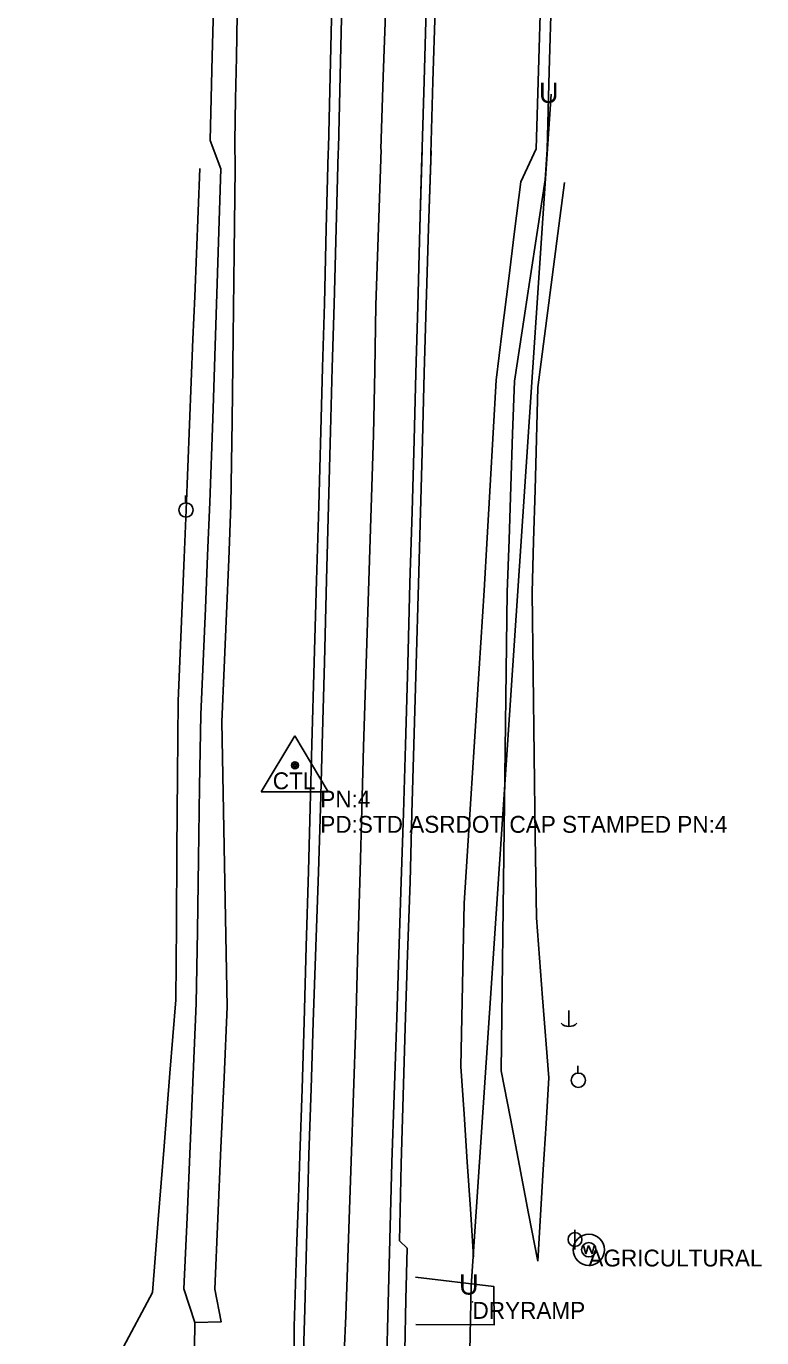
# Model space of a CAD drawing. Extents: x 1445297 to 1476720, y 2042269 to 2057889.
# Drawn here: x 1446022.3 to 1446240.4, y 2044766.6 to 2045155.5 of the extents above; entities that cross this region are included whole.
import ezdxf

# ---------------------------------------------------------------- set-up
doc = ezdxf.new("R2010")
doc.units = 0
for name, color, linetype in [('S_DITCHLINE', 7, 'Continuous'), ('S_DRIVEWAY', 7, 'Continuous'), ('S_EDGE_PAVEMENT', 7, 'Continuous'), ('S_MSC_PT_SYM', 7, 'Continuous'), ('S_PAVEMENT_CROWN', 7, 'Continuous'), ('S_PRIMARY_CTL', 7, 'Continuous'), ('S_PRIMARY_CTL_ANNOT', 7, 'Continuous'), ('S_SHOULDER', 7, 'Continuous'), ('S_SURVEY_TEXT_ANNOT', 7, 'Continuous'), ('S_UNDERGROUND_CABLE', 7, 'Continuous'), ('S_UTILITY_POLE', 7, 'Continuous'), ('S_UTL_PT_SYM', 7, 'Continuous'), ('S_WATER_WELL', 7, 'Continuous'), ('S_WATER_WELL_ANNOT', 7, 'Continuous')]:
    doc.layers.add(name, color=color, linetype=linetype)

msp = doc.modelspace()

# ---------------------------------------------------------------- linework, layer by layer
at = {"layer": 'S_DITCHLINE'}
for points in [[(1446072.33, 2044771.09), (1446069.05, 2044781.13), (1446069.97, 2044802.28), (1446070.88, 2044823.43), (1446071.79, 2044844.59), (1446072.7, 2044865.74), (1446073.04, 2044887.14), (1446073.37, 2044908.54), (1446073.71, 2044929.94), (1446074.04, 2044951.34), (1446074.72, 2044967.08), (1446075.4, 2044982.82), (1446076.08, 2044998.56), (1446076.76, 2045014.3), (1446077.58, 2045039.02), (1446078.4, 2045063.73), (1446079.21, 2045088.45), (1446080.03, 2045113.16), (1446076.86, 2045121.6), (1446077.47, 2045146.56), (1446078.08, 2045171.52)], [(1446154.93, 2044790.57), (1446154, 2044804.68), (1446153.07, 2044818.79), (1446152.13, 2044832.9), (1446151.2, 2044847.01), (1446151.69, 2044871.22), (1446152.19, 2044895.44), (1446153.66, 2044918.62), (1446155.14, 2044941.81), (1446156.61, 2044964.99), (1446158.09, 2044988.17), (1446158.97, 2045003.75), (1446159.84, 2045019.32), (1446160.72, 2045034.9), (1446161.6, 2045050.48), (1446163.43, 2045065.18), (1446165.26, 2045079.89), (1446167.09, 2045094.59), (1446168.92, 2045109.3), (1446173.55, 2045119.16), (1446174.22, 2045142.36), (1446174.88, 2045165.56)], [(1446163.17, 2044845.71), (1446163.43, 2044869.9), (1446163.68, 2044894.09), (1446164, 2044917.47), (1446164.31, 2044940.86), (1446164.62, 2044964.24), (1446164.93, 2044987.63), (1446165.47, 2045003.29), (1446166, 2045018.95), (1446166.54, 2045034.61), (1446167.08, 2045050.27), (1446169.35, 2045065.19), (1446171.62, 2045080.12), (1446173.88, 2045095.04), (1446176.15, 2045109.96), (1446176.78, 2045118.94), (1446177.41, 2045142.16), (1446178.04, 2045165.38)], [(1446072.06, 2044755.83), (1446072.33, 2044771.09), (1446080.14, 2044771.35), (1446078.2, 2044781), (1446079.12, 2044801.93), (1446080.03, 2044822.86), (1446080.94, 2044843.78), (1446081.86, 2044864.71), (1446081.47, 2044885.83), (1446081.09, 2044906.95), (1446080.7, 2044928.07), (1446080.32, 2044949.19), (1446080.99, 2044965.26), (1446081.65, 2044981.32), (1446082.32, 2044997.38), (1446082.99, 2045013.45), (1446083.31, 2045038.44), (1446083.64, 2045063.43), (1446083.96, 2045088.42), (1446084.29, 2045113.41), (1446084.18, 2045121.29), (1446084.39, 2045133.79), (1446084.6, 2045146.3), (1446084.8, 2045158.81)], [(1446059.69, 2044779.98), (1446061.43, 2044801.68), (1446063.17, 2044823.37), (1446064.91, 2044845.07), (1446066.65, 2044866.76), (1446066.82, 2044888.93), (1446066.99, 2044911.1), (1446067.16, 2044933.26), (1446067.33, 2044955.43), (1446067.91, 2044969.58), (1446068.5, 2044983.73), (1446069.08, 2044997.88), (1446069.67, 2045012.03), (1446070.19, 2045024.68), (1446070.7, 2045037.34), (1446071.22, 2045049.99), (1446071.73, 2045062.64), (1446072.25, 2045075.3), (1446072.76, 2045087.95), (1446073.28, 2045100.6), (1446073.79, 2045113.25)], [(1446059.69, 2044779.98), (1446061.43, 2044801.68), (1446063.17, 2044823.37), (1446064.91, 2044845.07), (1446066.65, 2044866.76), (1446066.82, 2044888.93), (1446066.99, 2044911.1), (1446067.16, 2044933.26), (1446067.33, 2044955.43), (1446067.91, 2044969.58), (1446068.5, 2044983.73), (1446069.08, 2044997.88), (1446069.67, 2045012.03), (1446070.19, 2045024.68), (1446070.7, 2045037.34), (1446071.22, 2045049.99), (1446071.73, 2045062.64), (1446072.25, 2045075.3), (1446072.76, 2045087.95), (1446073.28, 2045100.6), (1446073.79, 2045113.25)], [(1446072.33, 2044771.09), (1446069.05, 2044781.13), (1446069.97, 2044802.28), (1446070.88, 2044823.43), (1446071.79, 2044844.59), (1446072.7, 2044865.74), (1446073.04, 2044887.14), (1446073.37, 2044908.54), (1446073.71, 2044929.94), (1446074.04, 2044951.34), (1446074.72, 2044967.08), (1446075.4, 2044982.82), (1446076.08, 2044998.56), (1446076.76, 2045014.3), (1446077.58, 2045039.02), (1446078.4, 2045063.73), (1446079.21, 2045088.45), (1446080.03, 2045113.16)], [(1446071.26, 2044710.05), (1446071.53, 2044725.31), (1446071.79, 2044740.57), (1446072.06, 2044755.83), (1446072.33, 2044771.09), (1446080.14, 2044771.35), (1446078.2, 2044781), (1446079.12, 2044801.93), (1446080.03, 2044822.86), (1446080.94, 2044843.78), (1446081.86, 2044864.71), (1446081.47, 2044885.83), (1446081.09, 2044906.95), (1446080.7, 2044928.07), (1446080.32, 2044949.19), (1446080.99, 2044965.26), (1446081.65, 2044981.32), (1446082.32, 2044997.38), (1446082.99, 2045013.45), (1446083.31, 2045038.44), (1446083.64, 2045063.43), (1446083.96, 2045088.42), (1446084.29, 2045113.41)], [(1446168.92, 2045109.3), (1446167.09, 2045094.59), (1446165.26, 2045079.89), (1446163.43, 2045065.18), (1446161.6, 2045050.48), (1446160.72, 2045034.9), (1446159.84, 2045019.32), (1446158.97, 2045003.75), (1446158.09, 2044988.17), (1446156.61, 2044964.99), (1446155.14, 2044941.81), (1446153.66, 2044918.62), (1446152.19, 2044895.44), (1446151.69, 2044871.22), (1446151.2, 2044847.01), (1446152.13, 2044832.9), (1446153.07, 2044818.79), (1446154, 2044804.68), (1446154.93, 2044790.57)], [(1446176.15, 2045109.96), (1446173.88, 2045095.04), (1446171.62, 2045080.12), (1446169.35, 2045065.19), (1446167.08, 2045050.27), (1446166.54, 2045034.61), (1446166, 2045018.95), (1446165.47, 2045003.29), (1446164.93, 2044987.63), (1446164.62, 2044964.24), (1446164.31, 2044940.86), (1446164, 2044917.47), (1446163.68, 2044894.09), (1446163.43, 2044869.9), (1446163.17, 2044845.71)], [(1446181.94, 2045109.16), (1446179.96, 2045093.96), (1446177.99, 2045078.77), (1446176.02, 2045063.57), (1446174.04, 2045048.37), (1446173.61, 2045033.16), (1446173.18, 2045017.96), (1446172.75, 2045002.75), (1446172.32, 2044987.54), (1446172.63, 2044963.44), (1446172.94, 2044939.34), (1446173.26, 2044915.24), (1446173.57, 2044891.14), (1446175.43, 2044867.41), (1446177.28, 2044843.68), (1446176.46, 2044830.08), (1446175.63, 2044816.49), (1446174.81, 2044802.9), (1446173.98, 2044789.31)], [(1446163.17, 2044845.71), (1446165.88, 2044831.61), (1446168.58, 2044817.51), (1446171.28, 2044803.41), (1446173.98, 2044789.31)], [(1446059.69, 2044779.98), (1446050.34, 2044762.42), (1446040.99, 2044744.86), (1446031.63, 2044727.3), (1446022.28, 2044709.74)]]:
    msp.add_lwpolyline(points, dxfattribs=at)
at = {"layer": 'S_DRIVEWAY'}
msp.add_lwpolyline([(1446137.77, 2044784.59), (1446160.92, 2044781.78), (1446161.02, 2044770.41), (1446137.87, 2044770.54)], dxfattribs=at)
at = {"layer": 'S_EDGE_PAVEMENT'}
for points in [[(1446104.51, 2044762.35), (1446104.92, 2044775.04), (1446105.49, 2044797.93), (1446106.07, 2044820.82), (1446106.74, 2044840.5), (1446107.42, 2044860.18), (1446108.2, 2044882.46), (1446108.98, 2044904.73), (1446109.53, 2044923.61), (1446110.08, 2044942.48), (1446110.71, 2044966.9), (1446111.35, 2044991.32), (1446111.93, 2045013.34), (1446112.52, 2045035.37), (1446113.05, 2045054.21), (1446113.58, 2045073.05), (1446114.17, 2045095.47), (1446114.77, 2045117.9), (1446114.85, 2045119.28), (1446115.39, 2045140.74), (1446115.92, 2045162.21)], [(1446129.22, 2044761.27), (1446129.55, 2044772.98), (1446130.14, 2044795.76), (1446130.73, 2044818.54), (1446131.43, 2044838.55), (1446132.14, 2044858.56), (1446132.83, 2044880.24), (1446133.51, 2044901.91), (1446134.12, 2044922.1), (1446134.73, 2044942.3), (1446135.41, 2044966.32), (1446136.09, 2044990.33), (1446136.69, 2045011.54), (1446137.29, 2045032.75), (1446137.86, 2045052.62), (1446138.43, 2045072.5), (1446139.04, 2045095.65), (1446139.61, 2045116.7), (1446139.74, 2045119.55), (1446140.3, 2045139.21), (1446140.91, 2045160.63)], [(1446129.22, 2044761.27), (1446129.55, 2044772.98), (1446130.14, 2044795.76), (1446130.73, 2044818.54), (1446131.43, 2044838.55), (1446132.14, 2044858.56), (1446132.83, 2044880.24), (1446133.51, 2044901.91), (1446134.12, 2044922.1), (1446134.73, 2044942.3), (1446135.41, 2044966.32), (1446136.09, 2044990.33), (1446136.69, 2045011.54), (1446137.29, 2045032.75), (1446137.86, 2045052.62), (1446138.43, 2045072.5), (1446139.04, 2045095.65), (1446139.66, 2045118.81)]]:
    msp.add_lwpolyline(points, dxfattribs=at)
at = {"layer": 'S_MSC_PT_SYM'}
msp.add_lwpolyline([(1446154.63, 2044777.19), (1446154.63, 2044777.24), (1446154.63, 2044777.19), (1446154.58, 2044777.19), (1446154.63, 2044777.19), (1446154.63, 2044777.14), (1446154.63, 2044777.19), (1446154.68, 2044777.19)], dxfattribs=at)
at = {"layer": 'S_PAVEMENT_CROWN'}
msp.add_lwpolyline([(1446116.61, 2044761.99), (1446117.03, 2044773.09), (1446117.84, 2044796.01), (1446118.66, 2044818.92), (1446119.33, 2044839.1), (1446119.99, 2044859.28), (1446120.67, 2044882.09), (1446121.35, 2044904.9), (1446121.85, 2044923.35), (1446122.34, 2044941.81), (1446123.11, 2044966.43), (1446123.87, 2044991.05), (1446124.56, 2045012.67), (1446125.26, 2045034.29), (1446125.62, 2045053.51), (1446125.99, 2045072.73), (1446126.76, 2045095.83), (1446127.52, 2045118.93), (1446127.44, 2045119.04), (1446128.16, 2045140.5), (1446128.89, 2045161.96)], dxfattribs=at)
at = {"layer": 'S_PRIMARY_CTL'}
for p, q in [((1446101.98, 2044945.01), (1446091.95, 2044928.5)), ((1446101.98, 2044945.01), (1446111.81, 2044928.5)), ((1446091.95, 2044928.5), (1446111.81, 2044928.5))]:
    msp.add_line(p, q, dxfattribs=at)
for radius in [1.04, 0.609, 0.344]:
    msp.add_circle((1446101.98, 2044936.31), radius, dxfattribs=at)
at = {"layer": 'S_SHOULDER'}
for points in [[(1446101.75, 2044762.2), (1446101.73, 2044769.88), (1446102.15, 2044782.56), (1446102.57, 2044795.25), (1446102.99, 2044807.93), (1446103.41, 2044820.61), (1446104.07, 2044840.43), (1446104.72, 2044860.24), (1446105.35, 2044882.57), (1446105.99, 2044904.9), (1446106.5, 2044923.76), (1446107.02, 2044942.63), (1446107.71, 2044966.88), (1446108.4, 2044991.13), (1446109.02, 2045013.27), (1446109.64, 2045035.41), (1446110.17, 2045054.32), (1446110.7, 2045073.22), (1446111.27, 2045095.53), (1446111.85, 2045117.84), (1446111.96, 2045119.38), (1446112.44, 2045140.66), (1446112.93, 2045161.93)], [(1446134.55, 2044762.73), (1446134.89, 2044777.96), (1446135.24, 2044793.19), (1446133.01, 2044795.35), (1446133.52, 2044818.08), (1446134.11, 2044838.33), (1446134.7, 2044858.57), (1446135.4, 2044880.18), (1446136.1, 2044901.78), (1446136.64, 2044922.06), (1446137.19, 2044942.34), (1446137.88, 2044966.23), (1446138.57, 2044990.13), (1446139.19, 2045011.35), (1446139.8, 2045032.58), (1446140.34, 2045052.65), (1446140.88, 2045072.72), (1446141.61, 2045095.61), (1446142.25, 2045115.81), (1446142.31, 2045117.74), (1446142.91, 2045139.1), (1446143.51, 2045160.46)], [(1446134.55, 2044762.73), (1446134.89, 2044777.96), (1446135.24, 2044793.19), (1446133.01, 2044795.35), (1446133.52, 2044818.08), (1446134.11, 2044838.33), (1446134.7, 2044858.57), (1446135.4, 2044880.18), (1446136.1, 2044901.78), (1446136.64, 2044922.06), (1446137.19, 2044942.34), (1446137.88, 2044966.23), (1446138.57, 2044990.13), (1446139.19, 2045011.35), (1446139.8, 2045032.58), (1446140.34, 2045052.65), (1446140.88, 2045072.72), (1446141.61, 2045095.61), (1446142.33, 2045118.49)]]:
    msp.add_lwpolyline(points, dxfattribs=at)
at = {"layer": 'S_UNDERGROUND_CABLE'}
for p, q in [((1446177.97, 2045135.28), (1446154.27, 2044781.92)), ((1446154.27, 2044781.92), (1446141.2, 2044230.61))]:
    msp.add_line(p, q, dxfattribs=at)
at = {"layer": 'S_UTILITY_POLE'}
for p, q in [((1446069.55, 2045014.17), (1446069.55, 2045016.28)), ((1446183.16, 2044863.58), (1446183.16, 2044858.86)), ((1446185.89, 2044845.09), (1446185.89, 2044847.19)), ((1446185.02, 2044792.79), (1446185.02, 2044798.57))]:
    msp.add_line(p, q, dxfattribs=at)
for centre, radius in [((1446069.67, 2045012.03), 2.13), ((1446186.01, 2044842.94), 2.13), ((1446185.02, 2044795.71), 2.05)]:
    msp.add_circle(centre, radius, dxfattribs=at)
msp.add_arc((1446183.23, 2044862.28), 3.41, 226.3972, 313.6028, dxfattribs=at)
at = {"layer": 'S_WATER_WELL'}
for p, q in [((1446187.58, 2044793.94), (1446188.24, 2044791.46)), ((1446188.24, 2044791.46), (1446189.06, 2044793.94)), ((1446189.06, 2044793.94), (1446190.1, 2044791.46)), ((1446190.1, 2044791.46), (1446190.68, 2044793.98))]:
    msp.add_line(p, q, dxfattribs=at)
for centre, radius in [((1446189.15, 2044792.68), 4.63), ((1446189.12, 2044792.68), 2.13)]:
    msp.add_circle(centre, radius, dxfattribs=at)

# ---------------------------------------------------------------- texts
at = {"layer": 'S_PRIMARY_CTL'}
msp.add_text('CTL', height=5, dxfattribs=at).set_placement((1446095.4, 2044929.23))
at = {"layer": 'S_PRIMARY_CTL_ANNOT'}
for s, p in [('PN:4', (1446109.49, 2044923.81)), ('PD:STD ASRDOT CAP STAMPED PN:4', (1446109.49, 2044916.31))]:
    msp.add_text(s, height=5, dxfattribs=at).set_placement(p)
at = {"layer": 'S_SURVEY_TEXT_ANNOT'}
msp.add_text('DRYRAMP', height=5, dxfattribs=at).set_placement((1446154.63, 2044772.19))
at = {"layer": 'S_UTL_PT_SYM'}
for p in [(1446174.34, 2045132.73), (1446150.64, 2044779.38)]:
    msp.add_text('U', height=6, dxfattribs=at).set_placement(p)
at = {"layer": 'S_WATER_WELL_ANNOT'}
msp.add_text('AGRICULTURAL', height=5, dxfattribs=at).set_placement((1446188.99, 2044787.71))

doc.saveas('drawing.dxf')
